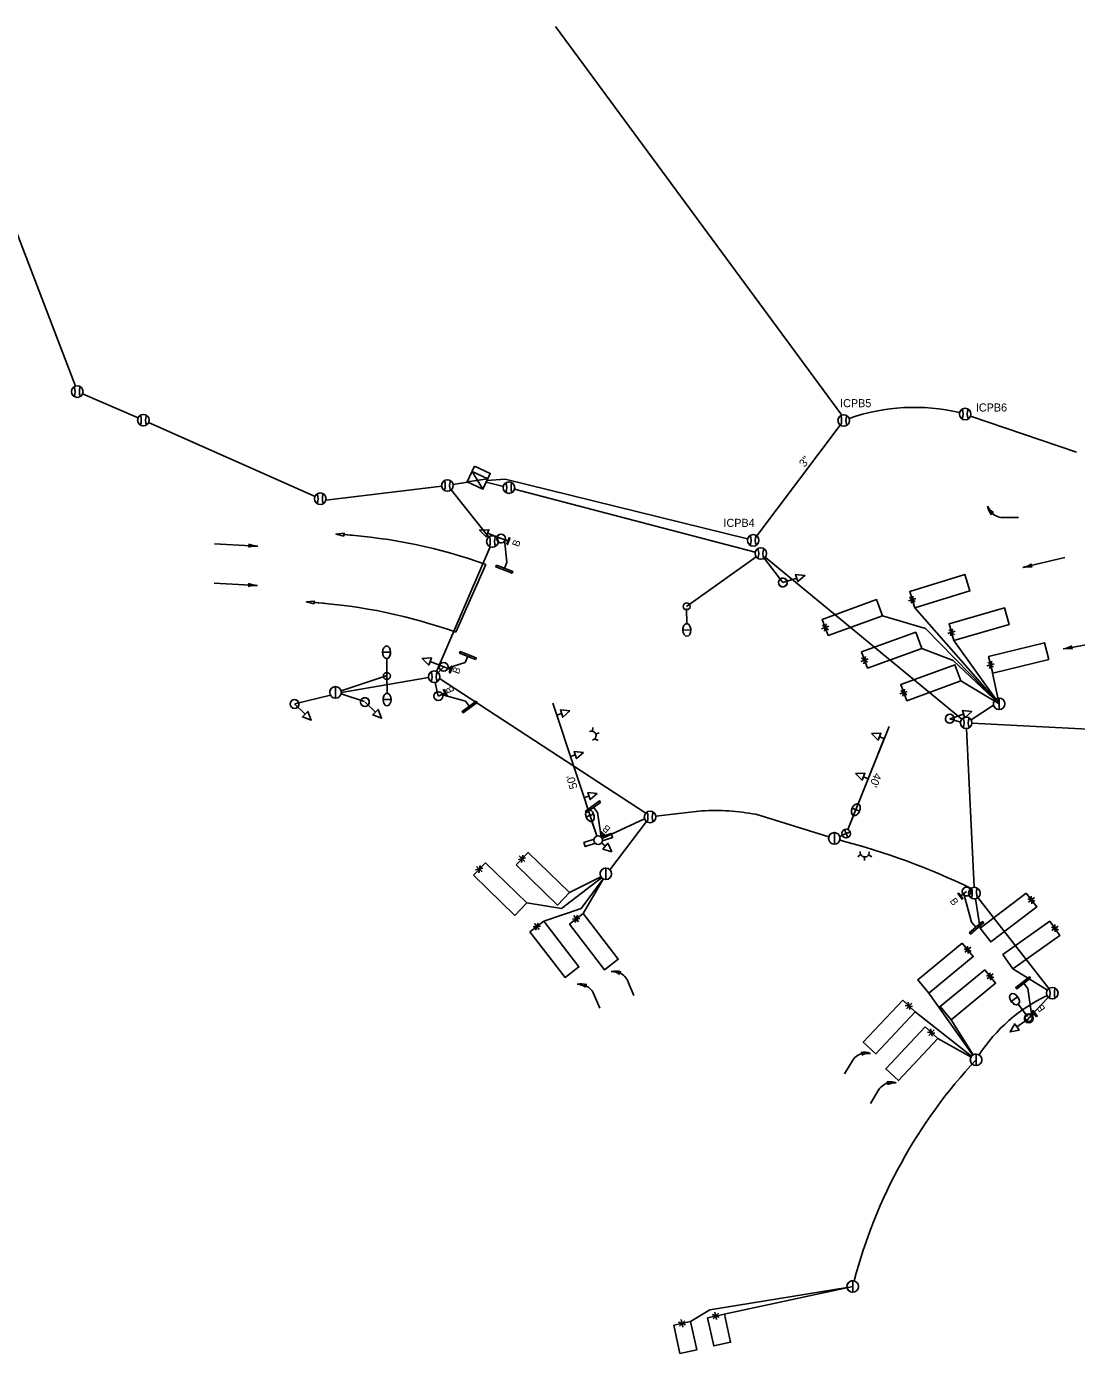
# Model space of a CAD drawing. Extents: x 596176 to 605330, y 332416 to 402398.
# Drawn here: x 603963.9 to 604328.3, y 349684.1 to 350144.4 of the extents above; entities that cross this region are included whole.
import ezdxf

# ---------------------------------------------------------------- set-up
doc = ezdxf.new("R2010")
doc.units = 0
for name, color, linetype in [('P_LTG', 7, 'Continuous'), ('P_SIG', 7, 'Continuous'), ('P_SIG_Bold', 7, 'Continuous'), ('P_SIG_Conduit', 7, 'Continuous'), ('P_SIG_IC', 7, 'Continuous'), ('P_SIG_Loops', 7, 'Continuous'), ('P_SIG_SignalHeads', 7, 'Continuous')]:
    doc.layers.add(name, color=color, linetype=linetype)

# ---------------------------------------------------------------- blocks, each defined once
blk = doc.blocks.new('_U260')
at = {"layer": 'P_SIG'}
blk.add_line((-0.385, 0.001), (0, 0), dxfattribs=at)
for points in [[(-0.611, 0.001), (-0.385, 0.101), (-0.385, -0.1), (-0.611, 0.001)], [(-0.385, 0.101), (-0.611, 0.001), (-0.385, -0.1), (-0.385, 0.101)], [(-0.611, 0.001), (-0.385, 0.101), (-0.385, -0.1), (-0.611, 0.001)]]:
    blk.add_lwpolyline(points, dxfattribs=at)
blk = doc.blocks.new('_U244')
at = {"layer": 'P_SIG'}
blk.add_circle((0, 0), 0.116, dxfattribs=at)
for start, end in [(0, 180), (180, 0)]:
    blk.add_arc((0, 0), 0.116, start, end, dxfattribs=at)
blk = doc.blocks.new('_U247')
at = {"layer": 'P_SIG_Bold'}
for p, q in [((-3.048, 0), (-0.114, 0)), ((-0.081, 0.081), (0.081, -0.081)), ((0.081, 0.081), (-0.081, -0.081))]:
    blk.add_line(p, q, dxfattribs=at)
blk.add_circle((0, 0), 0.114, dxfattribs=at)
blk.add_text("40'", height=0.2134, dxfattribs=at).set_placement((-1.787, 0.092))
blk = doc.blocks.new('_U248')
at = {"layer": 'P_SIG_Bold'}
blk.add_line((-0.114, 0), (-3.81, 0), dxfattribs=at)
for points in [[(-0.057, 0.098), (-0.057, 0.38), (0.058, 0.38), (0.058, 0.098)], [(0.058, -0.1), (0.058, -0.382), (-0.057, -0.382), (-0.057, -0.1)]]:
    blk.add_lwpolyline(points, dxfattribs=at)
blk.add_circle((0.001, -0.001), 0.114, dxfattribs=at)
at = {"layer": 'P_SIG'}
blk.add_text("50'", height=0.2134, rotation=178.0381, dxfattribs=at).set_placement((-1.484, -0.08))
blk = doc.blocks.new('LUMINAIRES_1')
at = {"layer": 'P_LTG'}
for p, q in [((4.3, 25.1), (-4.1, 25.1)), ((0, 2.3), (0, 18.4))]:
    blk.add_line(p, q, dxfattribs=at)
blk.add_circle((0, 0.1), 3.68, dxfattribs=at)
blk.add_ellipse((0.1, 25.1), major_axis=(0, 6.65), ratio=0.636439, dxfattribs=at)
blk.add_ellipse((0.1, 25.1), major_axis=(0, 6.65), ratio=0.636439, start_param=1.570796, end_param=4.712389, dxfattribs=at)
blk = doc.blocks.new('_U249')
at = {"layer": 'P_LTG'}
for p, q in [((4.3, 25.1), (-4.1, 25.1)), ((0, 2.3), (0, 18.4))]:
    blk.add_line(p, q, dxfattribs=at)
blk.add_ellipse((0.1, 25.1), major_axis=(0, 6.65), ratio=0.636439, dxfattribs=at)
blk.add_ellipse((0.1, 25.1), major_axis=(0, 6.65), ratio=0.636439, start_param=1.570796, end_param=4.712389, dxfattribs=at)
blk = doc.blocks.new('HEAD - TEMPORARY_2')
at = {"layer": 'P_SIG'}
blk.add_line((0.135, 0), (0, 0), dxfattribs=at)
blk.add_lwpolyline([(0.36, 0), (0.135, -0.1), (0.135, 0.1)], close=True, dxfattribs=at)
blk = doc.blocks.new('PUSH BUTTON')
at = {"layer": 'P_SIG'}
blk.add_line((0, 0), (7.6, 0), dxfattribs=at)
blk.add_lwpolyline([(7.6, -3.7), (7.6, 3.7), (8.6, 3.7), (8.6, -3.7)], close=True, dxfattribs=at)
blk.add_text('B', height=7.68, rotation=90, dxfattribs=at).set_placement((20.6, -2.6))
blk = doc.blocks.new('CONTROL CABINET_3')
at = {"layer": 'P_SIG'}
for p, q in [((-0.114, 0.076), (0.114, 0.076)), ((-0.114, 0.076), (0.114, -0.076)), ((0.114, 0.076), (-0.114, -0.076))]:
    blk.add_line(p, q, dxfattribs=at)
blk.add_lwpolyline([(-0.114, 0.152), (0.114, 0.152), (0.114, -0.076), (-0.114, -0.076)], close=True, dxfattribs=at)
blk = doc.blocks.new('_U256')
at = {"layer": 'P_SIG_Loops'}
for p, q in [((-0.055, -0.084), (0.052, 0.081)), ((0.056, -0.083), (-0.053, 0.082)), ((0, 0), (0, -0.229)), ((-0.105, -0.001), (0.099, -0.001))]:
    blk.add_line(p, q, dxfattribs=at)
blk.add_lwpolyline([(0, -0.229), (1.524, -0.229), (1.524, 0.229), (0, 0.229)], close=True, dxfattribs=at)
blk = doc.blocks.new('_U257')
at = {"layer": 'P_SIG_Loops'}
for p, q in [((-0.055, -0.084), (0.052, 0.081)), ((0.056, -0.083), (-0.053, 0.082)), ((-0.105, -0.001), (0.099, -0.001))]:
    blk.add_line(p, q, dxfattribs=at)
blk.add_lwpolyline([(0, -0.229), (0.762, -0.229), (0.762, 0.229), (0, 0.229)], close=True, dxfattribs=at)
blk = doc.blocks.new('_U212')
at = {"layer": 'P_SIG'}
blk.add_circle((0, 0), 6.1, dxfattribs=at)
for centre, start, end in [((-15.5, 0.1), 336.6741, 22.5272), ((15.5, 0.1), 157.5751, 203.4282)]:
    blk.add_arc(centre, 13.3, start, end, dxfattribs=at)
blk = doc.blocks.new('_U211')
at = {"layer": 'P_SIG'}
blk.add_line((0, 6.1), (0, -6.1), dxfattribs=at)
blk.add_lwpolyline([(0, -6.1), (0, 6.1)], dxfattribs=at)
blk.add_circle((0, 0), 6.1, dxfattribs=at)
for start, end in [(89.7008, 180), (180, 269.7008)]:
    blk.add_arc((0, 0), 6.1, start, end, dxfattribs=at)
blk = doc.blocks.new('_U269')
at = {"layer": 'P_SIG'}
blk.add_line((-0.017, -0.02), (-0.975, -0.02), dxfattribs=at)
blk.add_lwpolyline([(-0.914, 0.018), (-0.975, -0.02), (-0.914, -0.058)], dxfattribs=at)
for centre, start, end in [((-1.158, 0.78), 270, 287.7623), ((-1.158, -0.819), 72.2377, 90)]:
    blk.add_arc(centre, 0.799, start, end, dxfattribs=at)
blk = doc.blocks.new('_U268')
at = {"layer": 'P_SIG'}
for p, q in [((-0.675, 0.115), (-0.743, 0.129)), ((-0.725, 0.057), (-0.743, 0.129)), ((-0.017, -0.02), (-0.443, -0.02))]:
    blk.add_line(p, q, dxfattribs=at)
for centre, radius, start, end in [((-0.479, 0.454), 0.392, 205.2667, 239.9151), ((-0.377, 0.361), 0.462, 189.3153, 221.1715), ((-0.412, 0.421), 0.442, 221.4708, 266.0347)]:
    blk.add_arc(centre, radius, start, end, dxfattribs=at)
blk = doc.blocks.new('_U270')
at = {"layer": 'P_SIG'}
for p, q in [((-0.725, -0.096), (-0.743, -0.168)), ((-0.675, -0.154), (-0.743, -0.168)), ((-0.017, -0.02), (-0.443, -0.02))]:
    blk.add_line(p, q, dxfattribs=at)
for centre, radius, start, end in [((-0.377, -0.401), 0.462, 138.8285, 170.6847), ((-0.479, -0.493), 0.392, 120.0849, 154.7333), ((-0.412, -0.46), 0.442, 93.9653, 138.5292)]:
    blk.add_arc(centre, radius, start, end, dxfattribs=at)
blk = doc.blocks.new('CONFIRMATION LIGHT')
at = {"layer": 'P_SIG'}
for p, q in [((-4.2, 3), (-7.5, 4.8)), ((0, 5.5), (0, 9.2)), ((4.3, 2.9), (7.3, 5.5))]:
    blk.add_line(p, q, dxfattribs=at)
blk.add_arc((0, 0.6), 4.81, 352.2462, 187.7538, dxfattribs=at)
blk = doc.blocks.new('_U280')
at = {"layer": 'P_LTG'}
for p, q in [((4.3, 25), (-4.2, 25)), ((0, 0), (0, 18.5)), ((0, 0), (0, -18.3)), ((-4.3, -25), (4.2, -25))]:
    blk.add_line(p, q, dxfattribs=at)
blk.add_circle((0, 0), 3.68, dxfattribs=at)
for centre, major_axis in [((0, 25), (0, 6.65)), ((0, -25), (0, -6.65))]:
    blk.add_ellipse(centre, major_axis=major_axis, ratio=0.636439, dxfattribs=at)
for centre, major_axis in [((0, 25), (0, 6.65)), ((0, -25), (0, -6.65))]:
    blk.add_ellipse(centre, major_axis=major_axis, ratio=0.636439, start_param=1.570796, end_param=4.712389, dxfattribs=at)
blk = doc.blocks.new('CONTROL CABINET_4')
at = {"layer": 'P_SIG'}
for p, q in [((-0.114, 0.076), (0.114, 0.076)), ((-0.114, 0.076), (0.114, -0.076)), ((0.114, 0.076), (-0.114, -0.076))]:
    blk.add_line(p, q, dxfattribs=at)
blk.add_lwpolyline([(-0.114, 0.152), (0.114, 0.152), (0.114, -0.076), (-0.114, -0.076)], close=True, dxfattribs=at)

msp = doc.modelspace()

# ---------------------------------------------------------------- linework, layer by layer
at = {"layer": 'P_SIG'}
for p, q in [((604130.57, 349958.59), (604129.79, 349966.36)), ((604130.57, 349958.59), (604129.73, 349956.35)), ((604116.18, 349923.79), (604117.06, 349926.02)), ((604108.68, 349922.29), (604111.02, 349921.41)), ((604116.18, 349923.79), (604109.85, 349921.85)), ((604106.83, 349912.14), (604109.1, 349913.17)), ((604116.21, 349910.43), (604107.96, 349912.65)), ((604116.21, 349910.43), (604117.64, 349908.5)), ((604253.19, 349876.5), (604261.57, 349897.38)), ((604162.08, 349871.7), (604160.65, 349873.63)), ((604162.08, 349871.7), (604163.31, 349863.35)), ((604163.31, 349863.35), (604163.97, 349864.1)), ((604291.89, 349833.65), (604289.16, 349843.57)), ((604291.89, 349833.65), (604293.43, 349831.81)), ((604311.36, 349810.71), (604309.88, 349812.6)), ((604311.36, 349810.71), (604312.75, 349801.06))]:
    msp.add_line(p, q, dxfattribs=at)
for points in [[(604127.01, 349957.51), (604132.63, 349955.4), (604132.42, 349954.84), (604126.8, 349956.95)], [(604119.76, 349924.81), (604114.18, 349927.01), (604114.4, 349927.57), (604119.99, 349925.37)], [(604110.59, 349920.28), (604111.44, 349922.53), (604111.74, 349922.41), (604110.9, 349920.17)], [(604109.6, 349912.07), (604108.61, 349914.26), (604108.91, 349914.39), (604109.89, 349912.21)], [(604119.94, 349910.37), (604115.11, 349906.8), (604115.47, 349906.32), (604120.29, 349909.89)], [(604163.11, 349875.27), (604158.28, 349871.72), (604157.93, 349872.2), (604162.76, 349875.76)], [(604164.87, 349863.31), (604163.07, 349864.89), (604163.28, 349865.13), (604165.09, 349863.55)], [(604291.08, 349830.01), (604295.67, 349833.88), (604296.06, 349833.42), (604291.47, 349829.55)], [(604312.29, 349814.32), (604307.57, 349810.61), (604307.2, 349811.08), (604311.92, 349814.79)]]:
    msp.add_lwpolyline(points, close=True, dxfattribs=at)
at = {"layer": 'P_SIG_Conduit'}
for p, q in [((603980.86, 350019.67), (603946.93, 350108.38)), ((604111.94, 349985.55), (604116.93, 349986.41)), ((604106.15, 349920.71), (604124.79, 349963.92)), ((604192.95, 349943.17), (604217.11, 349960.45)), ((604219.95, 349960.02), (604226.39, 349951.56)), ((604073.08, 349913.99), (604089.08, 349919.26)), ((604108.68, 349922.29), (604106.75, 349920.31)), ((604106.78, 349912.12), (604105.71, 349916.91)), ((604056.98, 349909.4), (604069.4, 349912.46)), ((604073.09, 349912.9), (604081.15, 349910.21)), ((604291.7, 349903.92), (604299.52, 349908.95)), ((604284.3, 349904.3), (604288.04, 349903.12))]:
    msp.add_line(p, q, dxfattribs=at)
for points in [[(604002.62, 350008.65), (603983.37, 350017)], [(604064.03, 349981.44), (604006.28, 350007.04)], [(604107.98, 349984.97), (604067.79, 349980.13)], [(604129.38, 349984.91), (604123.4, 349986.31)], [(604133.26, 349983.95), (604216.8, 349962.12)], [(604124.33, 349967.32), (604111.22, 349983.65)], [(604220.28, 349960.34), (604288.47, 349904.11)], [(604073.16, 349913.43), (604103.38, 349918.55)], [(604178.78, 349871.52), (604107.24, 349918.2)], [(604290.11, 349900.84), (604292.75, 349845.79)], [(604292.01, 349902.73), (604397.1, 349897.32)], [(604178.42, 349869.5), (604163.72, 349862.77)], [(604179.05, 349868.64), (604166.34, 349851.87)], [(604182.27, 349870.5), (604198.27, 349872.32)], [(604216.98, 349871.12), (604242.33, 349863.33)], [(604246.13, 349863.45), (604247, 349863.78)], [(604294.07, 349842.22), (604318.65, 349810.64)], [(604318.51, 349807.62), (604311.65, 349800.39)]]:
    msp.add_lwpolyline(points, dxfattribs=at)
for centre, radius, start, end in [((604202.76, 349795.81), 76.64, 79.3075, 93.3542), ((604185.94, 349627.99), 241.78, 64.0669, 75.5796), ((604342.64, 349756.31), 57.45, 115.3257, 146.943), ((604423.75, 349664.09), 178.42, 136.9226, 165.3437)]:
    msp.add_arc(centre, radius, start, end, dxfattribs=at)
at = {"layer": 'P_SIG_IC'}
for points in [[(604246.84, 350009.64), (604147.46, 350144.44)], [(604291.54, 350009.29), (604328.28, 349996.72)], [(604217.31, 349967.77), (604246.3, 350006.16)], [(604123.7, 349986.96), (604130, 349987.37), (604214.16, 349966.67)]]:
    msp.add_lwpolyline(points, dxfattribs=at)
msp.add_arc((604272.03, 349944.21), 68.12, 76.6758, 109.4161, dxfattribs=at)
at = {"layer": 'P_SIG_Loops'}
for p, q in [((604123.26, 349957.84), (604112.95, 349934.29)), ((604293.18, 349841.82), (604294.91, 349831.65)), ((604306.23, 349817.56), (604318.18, 349810.12))]:
    msp.add_line(p, q, dxfattribs=at)
for points in [[(604074.08, 349967.68), (604071.32, 349968.37), (604074.15, 349968.61)], [(604063.77, 349944.13), (604061.02, 349944.82), (604063.85, 349945.06)]]:
    msp.add_lwpolyline(points, close=True, dxfattribs=at)
for points in [[(604074.11, 349968.15), (604077.24, 349967.89)], [(604063.81, 349944.59), (604066.93, 349944.34)], [(604272.16, 349942.74), (604301.45, 349909.48)], [(604260.93, 349939.98), (604275.94, 349935.59), (604301.45, 349909.48)], [(604274.57, 349928.67), (604285.5, 349924.46), (604301.45, 349909.47)], [(604285.75, 349931.41), (604301.45, 349909.48)], [(604299.19, 349920.09), (604301.44, 349909.48)], [(604288.14, 349917.38), (604301.45, 349909.48)], [(604163.47, 349849.09), (604149.56, 349838.48), (604137.52, 349840.38)], [(604143.38, 349834.02), (604156.42, 349838.48), (604163.97, 349848.7)], [(604152.33, 349843.97), (604163.24, 349849.39)], [(604157.05, 349836.71), (604164.02, 349848.67)], [(604292.27, 349787.58), (604276.99, 349809.11)], [(604272.35, 349802.59), (604291.85, 349787.19)], [(604284.75, 349799.85), (604292.37, 349787.65)], [(604280.12, 349793.33), (604291.68, 349786.92)], [(604248.66, 349706.98), (604201, 349699.26), (604194.36, 349695.13)], [(604206.07, 349697.73), (604250.64, 349707.3)]]:
    msp.add_lwpolyline(points, dxfattribs=at)
for centre in [(604061.51, 349785.54), (604051.21, 349761.98)]:
    msp.add_arc(centre, 183.03, 70.2859, 86.1613, dxfattribs=at)

# ---------------------------------------------------------------- block references
at = {"layer": 'P_LTG'}
for name, p, xscale, yscale, rotation in [('LUMINAIRES_1', (604192.97, 349943.29), 0.3280833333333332, 0.32808333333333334, -179.14755096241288), ('_U280', (604088.96, 349919.15), 0.32808333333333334, 0.3280833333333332, -179.40361482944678), ('_U249', (604162.11, 349862.92), 0.3280833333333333, 0.32808333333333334, 19.32575717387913), ('_U249', (604248.61, 349865.13), 0.3280833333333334, 0.32808333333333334, -22.19330309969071), ('LUMINAIRES_1', (604311.73, 349800.43), 0.3280833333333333, 0.32808333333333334, 37.30974535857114)]:
    msp.add_blockref(name, p, dxfattribs=dict(at, xscale=xscale, yscale=yscale, rotation=rotation))
at = {"layer": 'P_SIG'}
for name, p, xscale, yscale, rotation in [('CONTROL CABINET_4', (604120.42, 349987.01), 26.285724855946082, 26.285724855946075, -24.747018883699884), ('CONTROL CABINET_3', (604120.42, 349987.01), 26.246666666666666, 26.246666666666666, -24.669234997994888), ('CONTROL CABINET_4', (604120.42, 349987.01), 26.24666666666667, 26.24666666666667, -24.846750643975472), ('_U268', (604308.35, 349974.38), 13.123333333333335, 13.123333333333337, 0.29033250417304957), ('_U260', (604128.61, 349966.78), 13.123333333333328, 13.12333333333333, -21.48301689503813), ('_U269', (604028.94, 349964.67), 13.123333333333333, 13.123333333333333, 177.08051879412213), ('_U244', (604128.61, 349966.78), 13.123333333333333, 13.123333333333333, 160.85244389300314), ('PUSH BUTTON', (604128.61, 349966.78), 0.32808333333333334, 0.32808333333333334, -19.438543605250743), ('_U269', (604324.43, 349960.48), 13.123333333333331, 13.123333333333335, 13.149163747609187), ('_U269', (604028.84, 349951.06), 13.123333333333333, 13.123333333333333, 177.08051879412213), ('_U244', (604226.39, 349951.56), 13.123333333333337, 13.123333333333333, -162.1158384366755), ('_U260', (604226.39, 349951.56), 13.123333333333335, 13.123333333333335, -162.1158384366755), ('_U269', (604338.54, 349931.52), 13.123333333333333, 13.123333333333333, 10.52994057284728), ('_U260', (604108.68, 349922.29), 13.123333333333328, 13.12333333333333, -21.48301689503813), ('_U244', (604108.68, 349922.29), 13.123333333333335, 13.123333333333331, -21.64588104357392), ('_U244', (604056.92, 349909.4), 13.123333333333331, 13.123333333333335, 136.489148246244), ('_U260', (604056.96, 349909.41), 13.123333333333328, 13.12333333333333, 135.88695012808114), ('_U244', (604081.34, 349910.06), 13.123333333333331, 13.123333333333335, 136.489148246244), ('_U260', (604081.38, 349910.07), 13.123333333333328, 13.12333333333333, 135.88695012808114), ('_U244', (604106.83, 349912.14), 13.123333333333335, 13.123333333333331, -21.64588104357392), ('_U248', (604162.33, 349862.21), 13.123333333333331, 13.123333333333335, -71.60358121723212), ('HEAD - TEMPORARY_2', (604147.93, 349905.52), 13.123333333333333, 13.123333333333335, 17.99154968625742), ('_U244', (604284.3, 349904.3), 13.123333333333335, 13.123333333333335, -162.1158384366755), ('_U260', (604284.3, 349904.3), 13.123333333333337, 13.123333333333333, -162.11583843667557), ('_U247', (604248.36, 349864.43), 13.123333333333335, 13.123333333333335, -111.8527022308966), ('HEAD - TEMPORARY_2', (604261.57, 349897.38), 13.123333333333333, 13.123333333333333, 157.76758633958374), ('HEAD - TEMPORARY_2', (604152.7, 349891.16), 13.123333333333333, 13.123333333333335, 17.99154968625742), ('HEAD - TEMPORARY_2', (604255.99, 349883.46), 13.123333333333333, 13.123333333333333, 157.76758633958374), ('HEAD - TEMPORARY_2', (604157.44, 349876.92), 13.123333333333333, 13.123333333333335, 17.99154968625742), ('HEAD - TEMPORARY_2', (604163.46, 349861.23), 13.123333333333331, 13.123333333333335, -40.99852585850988), ('_U244', (604290.14, 349844.31), 13.123333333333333, 13.123333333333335, 36.20208107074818), ('PUSH BUTTON', (604290.14, 349844.31), 0.3280833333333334, 0.32808333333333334, -143.74221098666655), ('_U270', (604175.01, 349808.17), 13.123333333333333, 13.123333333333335, -67.28010227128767), ('_U270', (604163.17, 349803.74), 13.123333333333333, 13.123333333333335, -67.28010227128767), ('PUSH BUTTON', (604311.65, 349800.39), 0.32808333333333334, 0.3280833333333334, 36.25778901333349), ('_U260', (604311.7, 349800.33), 13.12333333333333, 13.123333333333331, 36.23789948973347), ('_U244', (604311.71, 349800.34), 13.123333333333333, 13.123333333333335, 36.20208107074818), ('_U268', (604247.89, 349780.73), 13.12333333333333, 13.123333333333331, -120.95667219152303), ('_U268', (604256.9, 349770.5), 13.12333333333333, 13.123333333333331, -120.95667219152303)]:
    msp.add_blockref(name, p, dxfattribs=dict(at, xscale=xscale, yscale=yscale, rotation=rotation))
at = {"layer": 'P_SIG_Conduit', "xscale": 0.32808333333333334, "yscale": 0.32808333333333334}
for name, p in [('_U212', (603981.53, 350017.78)), ('_U212', (604004.46, 350007.85)), ('_U212', (604109.97, 349985.21)), ('_U212', (604131.33, 349984.45)), ('_U212', (604065.85, 349980.62)), ('_U212', (604125.58, 349965.76)), ('_U212', (604218.73, 349961.61)), ('_U212', (604105.36, 349918.87)), ('_U211', (604071.16, 349913.42)), ('_U211', (604301.45, 349909.47)), ('_U212', (604290.02, 349902.84)), ('_U212', (604180.29, 349870.2)), ('_U211', (604244.25, 349862.77)), ('_U211', (604164.94, 349850.45)), ('_U212', (604292.84, 349843.79)), ('_U212', (604319.88, 349809.06)), ('_U211', (604293.42, 349785.95)), ('_U211', (604250.64, 349707.3))]:
    msp.add_blockref(name, p, dxfattribs=at)
at = {"layer": 'P_SIG_IC', "xscale": 0.32808333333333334, "yscale": 0.32808333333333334}
for p in [(604289.67, 350010), (604247.51, 350007.76), (604216.1, 349966.17)]:
    msp.add_blockref('_U212', p, dxfattribs=at)
at = {"layer": 'P_SIG_Loops'}
for name, p, xscale, yscale, rotation in [('_U256', (604271.28, 349945.61), 13.123333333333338, 13.123333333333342, 17.156179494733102), ('_U256', (604241.11, 349935.94), 13.123333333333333, 13.123333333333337, 20.049305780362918), ('_U256', (604284.92, 349934.29), 13.123333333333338, 13.123333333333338, 16.092772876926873), ('_U256', (604254.75, 349924.63), 13.123333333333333, 13.123333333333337, 20.049305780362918), ('_U256', (604298.49, 349923.01), 13.123333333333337, 13.123333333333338, 13.642930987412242), ('_U256', (604268.32, 349913.35), 13.123333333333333, 13.123333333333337, 20.049305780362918), ('_U256', (604121.06, 349852.12), 13.12333333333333, 13.12333333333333, -44.04414256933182), ('_U256', (604135.87, 349855.72), 13.12333333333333, 13.12333333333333, -44.04414256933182), ('_U256', (604312.65, 349841.37), 13.123333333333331, 13.12333333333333, -142.7570431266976), ('_U256', (604154.67, 349834.88), 13.12333333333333, 13.12333333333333, -52.42903853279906), ('_U256', (604141.01, 349832.19), 13.12333333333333, 13.12333333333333, -52.42903853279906), ('_U256', (604320.82, 349831.56), 13.12333333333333, 13.12333333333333, -144.7199303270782), ('_U256', (604290.56, 349824.09), 13.123333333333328, 13.12333333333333, -140.7002047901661), ('_U256', (604298.33, 349814.84), 13.123333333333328, 13.12333333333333, -140.7002047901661), ('_U256', (604270.16, 349804.63), 13.123333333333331, 13.12333333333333, -133.05283831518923), ('_U256', (604277.92, 349795.38), 13.123333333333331, 13.12333333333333, -133.05283831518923), ('_U257', (604203.14, 349697.08), 13.123333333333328, 13.12333333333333, -77.46116857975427), ('_U257', (604191.43, 349694.48), 13.123333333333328, 13.12333333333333, -77.46116857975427)]:
    msp.add_blockref(name, p, dxfattribs=dict(at, xscale=xscale, yscale=yscale, rotation=rotation))
at = {"layer": 'P_SIG_SignalHeads', "yscale": 0.32808333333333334}
for p, xscale, rotation in [((604159.81, 349898.36), 0.3280833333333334, -70.40606078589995), ((604254.82, 349858.1), 0.3280833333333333, 177.64680052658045)]:
    msp.add_blockref('CONFIRMATION LIGHT', p, dxfattribs=dict(at, xscale=xscale, rotation=rotation))

# ---------------------------------------------------------------- texts
at = {"layer": 'P_SIG'}
for rotation, p in [(69.3557, (604113.89, 349919.58)), (114.295, (604112.44, 349913.86)), (138.8667, (604166.8, 349866.24))]:
    msp.add_text('B', height=2.52, rotation=rotation, dxfattribs=at).set_placement(p)
at = {"layer": 'P_SIG_IC'}
for s, p in [('ICPB5', (604246.27, 350012.36)), ('ICPB6', (604293.37, 350010.87)), ('ICPB4', (604205.78, 349970.84))]:
    msp.add_text(s, height=2.8, dxfattribs=at).set_placement(p)
msp.add_text('3"', height=2.8, rotation=51.946, dxfattribs=at).set_placement((604233.95, 349991.33))

doc.saveas('drawing.dxf')
